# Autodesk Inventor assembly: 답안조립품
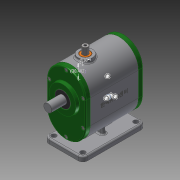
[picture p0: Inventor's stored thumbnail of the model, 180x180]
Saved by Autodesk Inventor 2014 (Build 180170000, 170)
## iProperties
Created: 2016-12
Part Number: 답안조립품
Document SubType Name: Assembly
Designer: user
Mass: 2541.06 g
Surface Area: 2013.6 cm^2
Volume: 724.4 cm^3
Density: 3.50781 g/cm^3
Author: user
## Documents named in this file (14)
- C:\Users\user\Desktop\361208V1019\답안조립품.iam
- C:\Users\user\Desktop\361208V1019\본체.ipt
- C:\Users\user\Desktop\361208V1019\앞커버.ipt
- C:\Users\user\Desktop\361208V1019\뒤커버.ipt
- C:\Users\user\Desktop\361208V1019\베어링 6003.ipt
- C:\Users\user\Desktop\361208V1019\베어링 608.ipt
- C:\Users\user\Desktop\361208V1019\오일실 17 32 8.ipt
- C:\Users\user\Desktop\361208V1019\오일실 8 22 7.ipt
- C:\Users\user\Desktop\361208V1019\서브축.ipt
- C:\Users\user\Desktop\361208V1019\메인축.ipt
- C:\Users\user\Desktop\361208V1019\부시.ipt
- C:\Users\user\Desktop\361208V1019\슬라이더.ipt
- C:\Users\user\Desktop\361208V1019\가변스프링.ipt
- C:\Users\user\Desktop\361208V1019\볼트 M4.ipt
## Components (1 placed, 1 different names)
1. 가변스프링:1 — Mate:4, Mate:5, Mate:6
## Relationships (3: Mate 3)
- Mate:4: 가변스프링:1
- Mate:5: 가변스프링:1
- Mate:6: 가변스프링:1
